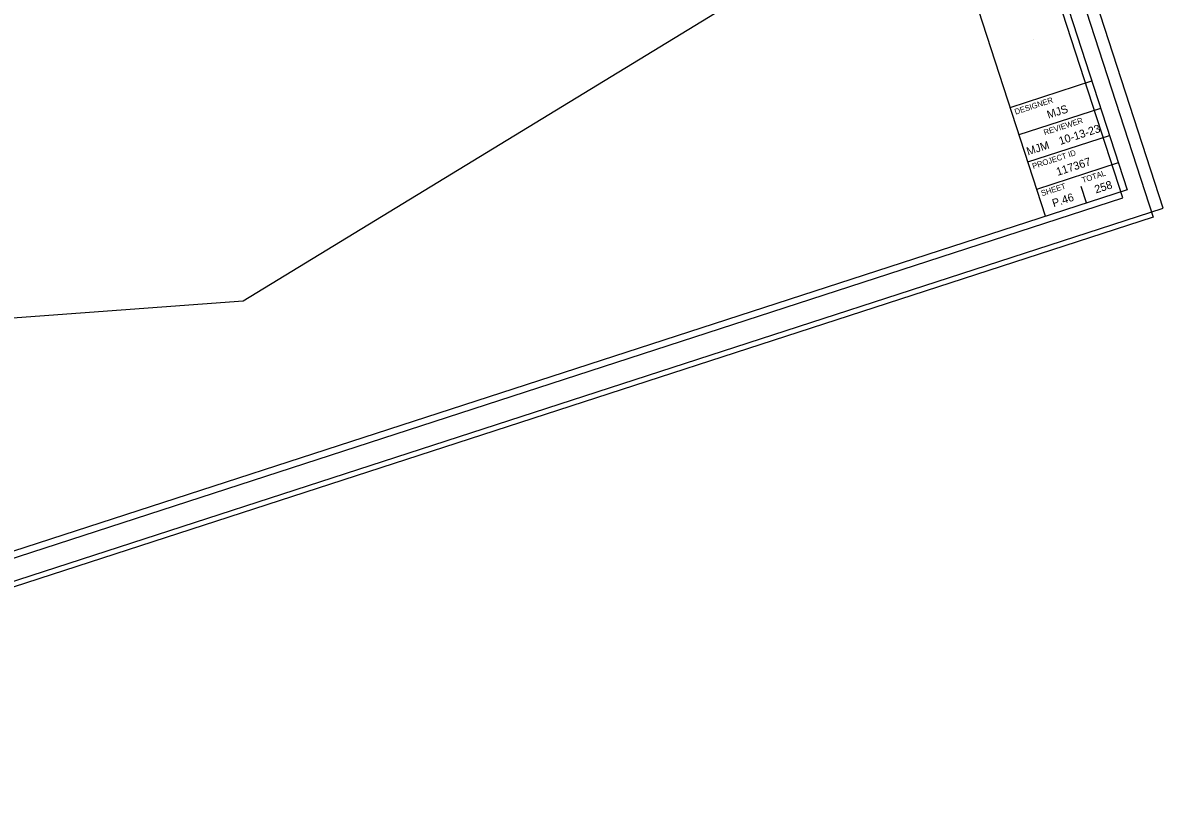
# Model space of a CAD drawing. Extents: x -468548933 to 3387700, y -306089263 to 1207014.
# Drawn here: x 1838071 to 1844053, y 531685 to 535853 of the extents above; entities that cross this region are included whole.
import ezdxf

# ---------------------------------------------------------------- set-up
doc = ezdxf.new("R2010")
doc.units = 0
for name, color, linetype in [('Level 63', 7, 'Continuous'), ('SC_Scratch1', 7, 'Continuous'), ('SH_Border', 7, 'Continuous'), ('SH_Cut_Line', 7, 'Continuous'), ('SH_Data', 7, 'Continuous')]:
    doc.layers.add(name, color=color, linetype=linetype)

msp = doc.modelspace()

# ---------------------------------------------------------------- linework, layer by layer
at = {"layer": 'Level 63'}
for points in [[(1832262, 537961.5), (1841962.9, 541110.9), (1844000.6, 534834.2), (1834299.8, 531684.7)], [(1834368.8, 531858.5), (1843842, 534934.1), (1841881.8, 540971.9), (1832408.6, 537896.3)]]:
    msp.add_lwpolyline(points, close=True, dxfattribs=at)
at = {"layer": 'SC_Scratch1'}
msp.add_lwpolyline([(1834448.4, 536360.5), (1835055.8, 534489.4), (1836664.2, 534206.2), (1839225.8, 534394.2), (1842361.7, 536308.3), (1842189.4, 536805.1), (1841581.8, 538676.6), (1840313.7, 539042.5), (1837357.7, 538260.2), (1834781, 538194.3), (1834403.1, 536496.4)], close=True, dxfattribs=at)
at = {"layer": 'SH_Border'}
for p, q in [((1843436.2, 534838.5), (1841490.8, 540830.6)), ((1843250.9, 535409.2), (1843678.9, 535548.2)), ((1843297.2, 535266.5), (1843725.2, 535405.5)), ((1843343.5, 535123.9), (1843771.5, 535262.8)), ((1843389.9, 534981.2), (1843817.9, 535120.2))]:
    msp.add_line(p, q, dxfattribs=at)
msp.add_lwpolyline([(1832787.9, 538005.2), (1841918.8, 540969.6), (1843864.2, 534977.5), (1834733.3, 532013.1)], close=True, dxfattribs=at)
at = {"layer": 'SH_Cut_Line'}
msp.add_lwpolyline([(1834351.6, 531731.5), (1844053.2, 534881.1), (1842015.1, 541158.6), (1832313.6, 538008.9)], close=True, dxfattribs=at)
at = {"layer": 'SH_Data'}
for p, q in [((1843372.3, 535764), (1843372.3, 535764)), ((1843650.2, 534908), (1843622.4, 534993.6)), ((1843527, 534923.2), (1843527, 534923.2))]:
    msp.add_line(p, q, dxfattribs=at)

# ---------------------------------------------------------------- texts
for s, height, p in [('DESIGNER', 30, (1843279.1, 535371)), ('MJS', 42, (1843451.2, 535349.7)), ('REVIEWER', 30, (1843431.5, 535262.8)), ('10-13-23', 42, (1843513.3, 535212.1)), ('MJM', 42, (1843343.9, 535157.1)), ('PROJECT ID', 30, (1843371.7, 535085.7)), ('117367', 42, (1843499.9, 535050.1)), ('TOTAL', 30, (1843632, 535012.5)), ('258', 42, (1843700.9, 534957.6)), ('SHEET', 30, (1843418, 534943)), ('P.46', 42, (1843478.6, 534885.4))]:
    msp.add_text(s, height=height, rotation=17.9864, dxfattribs=at).set_placement(p)

doc.saveas('drawing.dxf')
